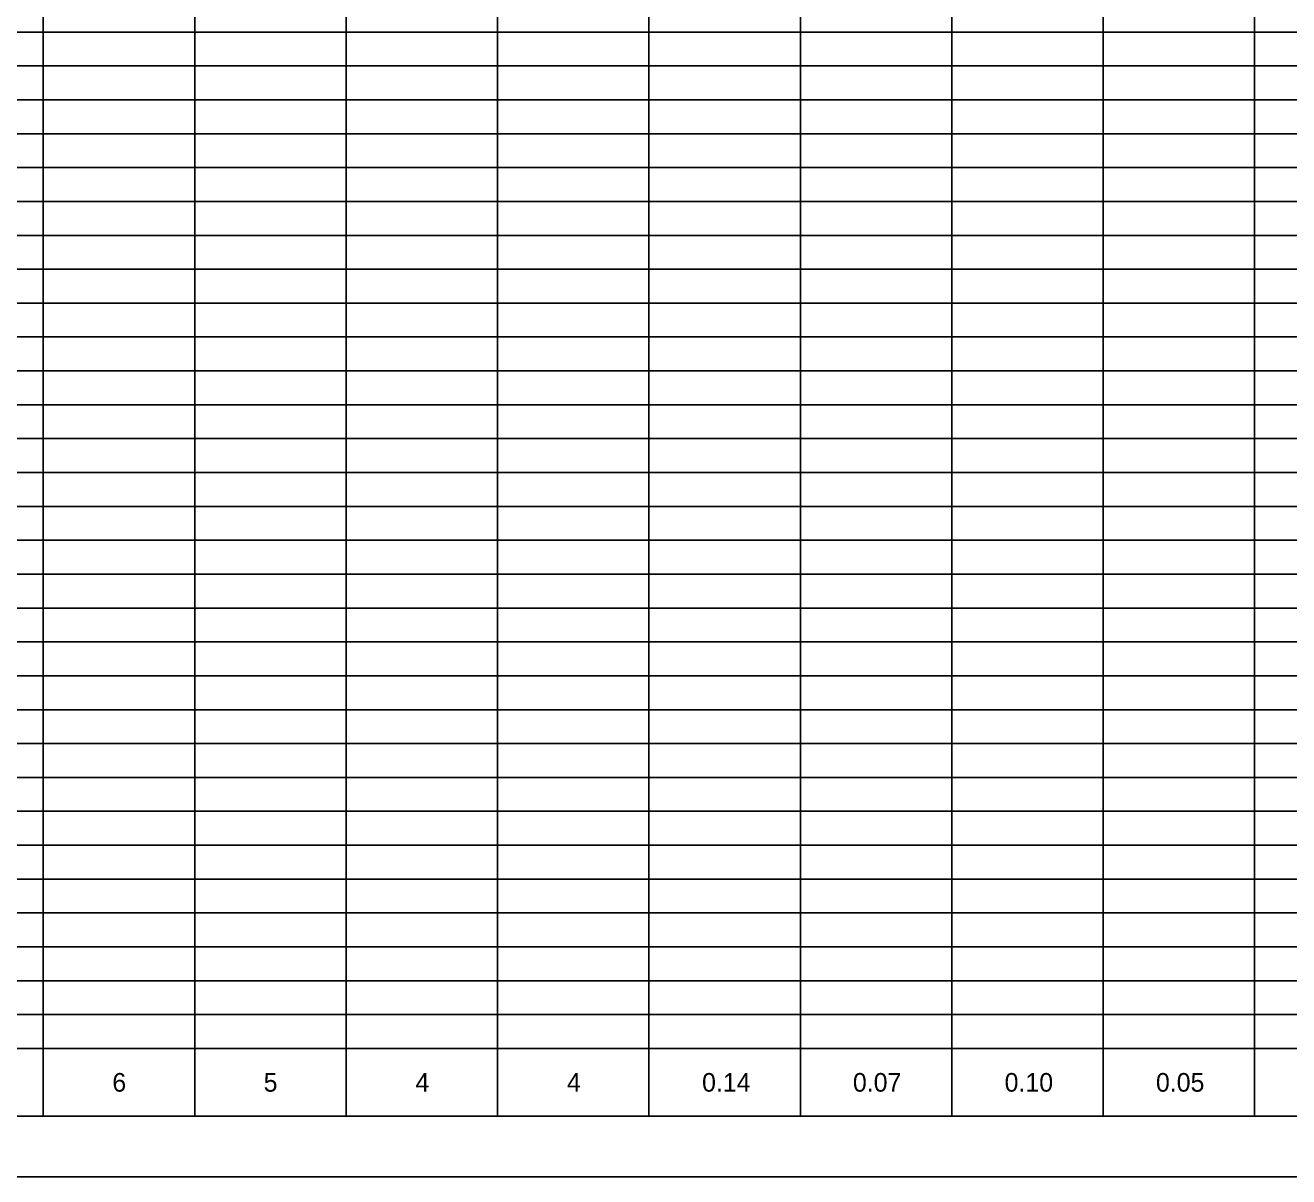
# Model space of a CAD drawing. Extents: x 0 to 34, y 0 to 22.
# Drawn here: x 13.11 to 23.56, y 0 to 9.52 of the extents above; entities that cross this region are included whole.
import ezdxf

# ---------------------------------------------------------------- set-up
doc = ezdxf.new("R2010")
doc.units = 0
for name, color, linetype in [('SH_Border', 7, 'Continuous'), ('SH_Cut_Line', 7, 'Continuous'), ('SH_Data', 7, 'Continuous'), ('SH_Text', 7, 'Continuous')]:
    doc.layers.add(name, color=color, linetype=linetype)

msp = doc.modelspace()

# ---------------------------------------------------------------- linework, layer by layer
at = {"layer": 'SH_Border'}
msp.add_lwpolyline([(1.5, 21.5), (33.5, 21.5), (33.5, 0.5), (1.5, 0.5)], close=True, dxfattribs=at)
at = {"layer": 'SH_Cut_Line'}
msp.add_lwpolyline([(0, 0), (34, 0), (34, 22), (0, 22)], close=True, dxfattribs=at)
at = {"layer": 'SH_Data'}
for p, q in [((13.26, 21.5), (13.26, 0.5)), ((14.512, 21.5), (14.512, 0.5)), ((15.764, 21.5), (15.764, 0.5)), ((17.015, 21.5), (17.015, 0.5)), ((18.267, 21.5), (18.267, 0.5)), ((19.519, 21.5), (19.519, 0.5)), ((20.771, 21.5), (20.771, 0.5)), ((22.022, 21.5), (22.022, 0.5)), ((23.274, 21.5), (23.274, 0.5)), ((1.5, 9.46), (32.02, 9.46)), ((1.5, 9.18), (32.02, 9.18)), ((1.5, 8.9), (32.02, 8.9)), ((1.5, 8.62), (32.02, 8.62)), ((1.5, 8.34), (32.02, 8.34)), ((1.5, 8.06), (32.02, 8.06)), ((1.5, 7.78), (32.02, 7.78)), ((1.5, 7.5), (32.02, 7.5)), ((1.5, 7.22), (32.02, 7.22)), ((1.5, 6.94), (32.02, 6.94)), ((1.5, 6.66), (32.02, 6.66)), ((1.5, 6.38), (32.02, 6.38)), ((1.5, 6.1), (32.02, 6.1)), ((1.5, 5.82), (32.02, 5.82)), ((1.5, 5.54), (32.02, 5.54)), ((1.5, 5.26), (32.02, 5.26)), ((1.5, 4.98), (32.02, 4.98)), ((1.5, 4.7), (32.02, 4.7)), ((1.5, 4.42), (32.02, 4.42)), ((1.5, 4.14), (32.02, 4.14)), ((1.5, 3.86), (32.02, 3.86)), ((1.5, 3.58), (32.02, 3.58)), ((1.5, 3.3), (32.02, 3.3)), ((1.5, 3.02), (32.02, 3.02)), ((1.5, 2.74), (32.02, 2.74)), ((1.5, 2.46), (32.02, 2.46)), ((1.5, 2.18), (32.02, 2.18)), ((1.5, 1.9), (32.02, 1.9)), ((1.5, 1.62), (32.02, 1.62)), ((1.5, 1.34), (32.02, 1.34)), ((1.5, 1.06), (32.02, 1.06)), ((1.5, 0.5), (32.02, 0.5))]:
    msp.add_line(p, q, dxfattribs=at)

# ---------------------------------------------------------------- texts
at = {"layer": 'SH_Text'}
for s, p in [('6', (13.831, 0.703)), ('5', (15.082, 0.703)), ('4', (16.337, 0.703)), ('4', (17.589, 0.703)), ('0.14', (18.706, 0.703)), ('0.07', (19.953, 0.703)), ('0.10', (21.207, 0.703)), ('0.05', (22.458, 0.703))]:
    msp.add_text(s, height=0.154, dxfattribs=at).set_placement(p)

doc.saveas('drawing.dxf')
